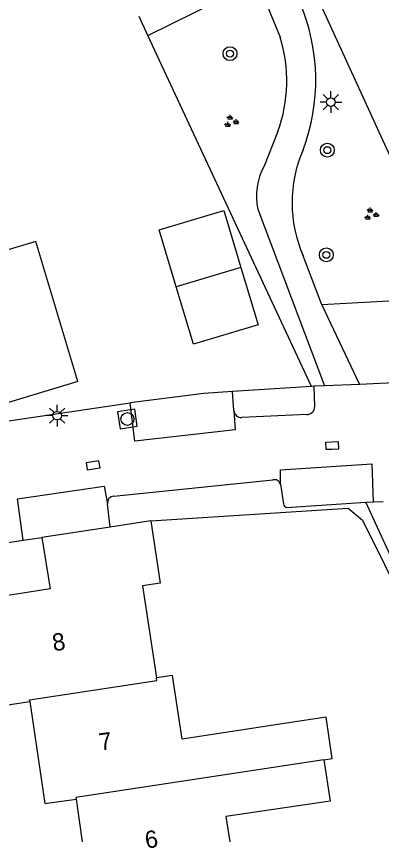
# Model space of a CAD drawing. Extents: x 128999 to 131010, y 395498 to 399007.
# Drawn here: x 130812.16 to 130833.26, y 395499.61 to 395547.75 of the extents above; entities that cross this region are included whole.
import ezdxf

# ---------------------------------------------------------------- set-up
doc = ezdxf.new("R2010")
doc.units = 0
for name, color, linetype in [('gg-afsc-erfafscheiding', 7, 'Continuous'), ('gg-anno-huisnummerreeks BGT', 7, 'Continuous'), ('gg-bbg-gedigitaliseerde bebouwing', 7, 'Continuous'), ('gg-bbg-gedigitaliseerde bijgebouw', 7, 'Continuous'), ('gg-bbg-hoofdgebouw', 7, 'Continuous'), ('gg-bbg-luifel en loopbrug', 7, 'Continuous'), ('gg-bbg-tussenscheiding', 7, 'Continuous'), ('gg-knt-onverhard', 7, 'Continuous'), ('gg-knt-verharding', 7, 'Continuous'), ('gg-knt-verharding nz', 7, 'Continuous'), ('gt-grn-groengrens', 7, 'Continuous'), ('gt-symb-boom', 7, 'Continuous'), ('gt-symb-groenvak', 7, 'Continuous'), ('gt-symb-kolk', 7, 'Continuous'), ('gt-symb-lichtmast', 7, 'Continuous'), ('gt-symb-rioolschacht', 7, 'Continuous')]:
    doc.layers.add(name, color=color, linetype=linetype)

# ---------------------------------------------------------------- blocks, each defined once
blk = doc.blocks.new('gt0-BOOM')
at = {"layer": 'gt-symb-boom'}
for radius in [0.4, 0.2]:
    blk.add_circle((0, 0), radius, dxfattribs=at)
blk = doc.blocks.new('gt0-LMAST')
at = {"layer": 'gt-symb-lichtmast'}
for p, q in [((-0.005, 0.246), (-0.005, 0.621)), ((-0.182, 0.173), (-0.447, 0.438)), ((0.172, 0.173), (0.437, 0.438)), ((-0.255, -0.004), (-0.63, -0.004)), ((-0.182, -0.181), (-0.447, -0.446)), ((-0.005, -0.254), (-0.005, -0.629)), ((0.437, -0.446), (0.172, -0.181)), ((0.245, -0.004), (0.62, -0.004))]:
    blk.add_line(p, q, dxfattribs=at)
blk.add_circle((-0.005, -0.004), 0.25, dxfattribs=at)
blk = doc.blocks.new('gt0-GRVAK')
at = {"layer": 'gt-symb-groenvak'}
for p, q in [((-0.11, 0.189), (-0.228, 0.24)), ((-0.182, 0.153), (0.088, 0.153)), ((-0.091, 0.211), (-0.156, 0.322)), ((-0.047, 0.214), (-0.047, 0.393)), ((-0.004, 0.211), (0.061, 0.322)), ((0.015, 0.189), (0.133, 0.24)), ((0.262, -0.052), (0.197, 0.059)), ((0.305, -0.049), (0.305, 0.13)), ((0.349, -0.052), (0.414, 0.059)), ((-0.245, -0.228), (-0.363, -0.177)), ((-0.318, -0.264), (-0.047, -0.264)), ((-0.226, -0.206), (-0.291, -0.095)), ((-0.183, -0.203), (-0.183, -0.024)), ((-0.139, -0.206), (-0.074, -0.095)), ((-0.12, -0.228), (-0.002, -0.177)), ((0.243, -0.074), (0.125, -0.023)), ((0.17, -0.11), (0.441, -0.11)), ((0.368, -0.074), (0.486, -0.023))]:
    blk.add_line(p, q, dxfattribs=at)
blk = doc.blocks.new('gt0-KOLK')
at = {"layer": 'gt-symb-kolk'}
blk.add_lwpolyline([(0, 0), (0.375, 0), (0.375, 0.4), (-0.375, 0.4), (-0.375, 0), (0, 0)], dxfattribs=at)
blk = doc.blocks.new('gt0-RS')
at = {"layer": 'gt-symb-rioolschacht'}
blk.add_lwpolyline([(-0.5, -0.5), (0.5, -0.5), (0.5, 0.5), (-0.5, 0.5)], close=True, dxfattribs=at)
blk.add_circle((0, 0), 0.375, dxfattribs=at)

msp = doc.modelspace()

# ---------------------------------------------------------------- linework, layer by layer
at = {"layer": 'gg-afsc-erfafscheiding'}
for p, q in [((130819.752, 395546.666), (130819.244, 395547.757)), ((130829.211, 395526.353), (130819.752, 395546.666))]:
    msp.add_line(p, q, dxfattribs=at)
for points in [[(130839.662, 395526.786), (130829.862, 395548.174), (130825.076, 395558.725), (130820.69, 395568.516)], [(130819.915, 395518.56), (130831.342, 395519.293), (130832.158, 395518.612), (130834.718, 395513.469), (130835.475, 395511.715), (130835.932, 395511.835)]]:
    msp.add_lwpolyline(points, dxfattribs=at)
at = {"layer": 'gg-bbg-gedigitaliseerde bebouwing'}
for points in [[(130815.694, 395526.641), (130813.26, 395534.74), (130811.34, 395534.15), (130810.271, 395537.61)], [(130819.915, 395518.56), (130820.456, 395514.968), (130819.44, 395514.81), (130820.25, 395509.48)], [(130827.76, 395506.85), (130821.73, 395505.94), (130821.17, 395509.62), (130820.25, 395509.48)], [(130829.928, 395504.74), (130830.416, 395504.814), (130830.054, 395507.198), (130827.76, 395506.85)], [(130829.928, 395504.74), (130830.29, 395502.35), (130824.26, 395501.45), (130824.482, 395500)]]:
    msp.add_lwpolyline(points, dxfattribs=at)
at = {"layer": 'gg-bbg-gedigitaliseerde bijgebouw'}
msp.add_line((130825.129, 395533.228), (130821.392, 395532.105), dxfattribs=at)
msp.add_lwpolyline([(130821.392, 395532.105), (130820.398, 395535.415), (130824.135, 395536.538), (130825.129, 395533.228)], dxfattribs=at)
at = {"layer": 'gg-bbg-hoofdgebouw'}
for p, q in [((130815.694, 395526.641), (130810.285, 395525)), ((130817.57, 395518.207), (130813.617, 395517.612)), ((130819.915, 395518.56), (130817.57, 395518.207)), ((130815.593, 395502.463), (130815.947, 395500))]:
    msp.add_line(p, q, dxfattribs=at)
for points in [[(130813.617, 395517.612), (130814.099, 395514.632), (130810.179, 395514.012), (130811.134, 395507.844), (130812.925, 395508.107)], [(130812.925, 395508.107), (130813.792, 395502.204), (130815.593, 395502.463)]]:
    msp.add_lwpolyline(points, dxfattribs=at)
at = {"layer": 'gg-bbg-luifel en loopbrug'}
msp.add_lwpolyline([(130825.129, 395533.228), (130826.124, 395529.918), (130822.387, 395528.795), (130821.392, 395532.105)], dxfattribs=at)
at = {"layer": 'gg-bbg-tussenscheiding'}
for points in [[(130812.925, 395508.107), (130812.909, 395508.214), (130820.274, 395509.321), (130820.25, 395509.48)], [(130829.928, 395504.74), (130815.579, 395502.562), (130815.593, 395502.463)]]:
    msp.add_lwpolyline(points, dxfattribs=at)
at = {"layer": 'gg-knt-onverhard'}
for p, q in [((130827.267, 395541.108), (130826.475, 395539.09)), ((130826.115, 395536.601), (130829.966, 395526.384)), ((130829.818, 395531.068), (130828.738, 395533.903))]:
    msp.add_line(p, q, dxfattribs=at)
msp.add_lwpolyline([(130819.752, 395546.666), (130825.304, 395549.415), (130826.209, 395549.473), (130827.393, 395546.555)], dxfattribs=at)
for centre, radius, start, end in [((130817.995, 395544.073), 11.465, 339.3759, 22.6568), ((130819.351, 395544.016), 8.433, 339.8287, 17.5211), ((130835.726, 395536.984), 7.637, 156.4505, 203.7924), ((130829.549, 395537.375), 3.52, 150.8379, 192.7021)]:
    msp.add_arc(centre, radius, start, end, dxfattribs=at)
at = {"layer": 'gg-knt-verharding'}
for p, q in [((130829.818, 395531.068), (130831.996, 395526.468)), ((130829.211, 395526.353), (130824.639, 395526.048)), ((130829.341, 395526.358), (130829.211, 395526.353)), ((130829.966, 395526.384), (130829.341, 395526.358)), ((130829.341, 395526.358), (130829.397, 395525.182)), ((130831.996, 395526.468), (130829.966, 395526.384)), ((130824.713, 395524.95), (130824.639, 395526.048)), ((130808.095, 395523.817), (130818.717, 395525.4)), ((130828.938, 395524.724), (130825.175, 395524.545)), ((130817.774, 395519.991), (130826.984, 395520.934)), ((130827.411, 395520.691), (130827.587, 395519.543)), ((130827.772, 395519.349), (130832.366, 395519.644)), ((130832.366, 395519.644), (130832.789, 395519.661)), ((130832.789, 395519.661), (130833.367, 395519.684)), ((130817.57, 395518.207), (130817.411, 395519.557)), ((130809.13, 395516.924), (130812.542, 395517.447)), ((130812.542, 395517.447), (130813.617, 395517.612))]:
    msp.add_line(p, q, dxfattribs=at)
for points in [[(130837.646, 395526.703), (130835.437, 395531.383), (130829.818, 395531.068)], [(130824.639, 395526.048), (130822.993, 395525.938), (130818.717, 395525.4)]]:
    msp.add_lwpolyline(points, dxfattribs=at)
for centre, radius, start, end in [((130825.164, 395524.998), 0.453, 186.0743, 271.4486), ((130828.953, 395525.168), 0.445, 268.1188, 1.7562), ((130827.087, 395520.618), 0.332, 12.6596, 108.0532), ((130817.794, 395519.605), 0.386, 93.0348, 187.1466), ((130827.825, 395519.585), 0.241, 189.9026, 257.3767)]:
    msp.add_arc(centre, radius, start, end, dxfattribs=at)
at = {"layer": 'gg-knt-verharding nz'}
msp.add_line((130837.646, 395526.703), (130831.996, 395526.468), dxfattribs=at)
for points in [[(130824.713, 395524.95), (130824.799, 395523.833), (130818.997, 395523.178), (130818.717, 395525.4)], [(130827.411, 395520.691), (130827.424, 395521.525), (130832.701, 395521.865), (130832.789, 395519.661)], [(130812.542, 395517.447), (130812.212, 395519.847), (130817.226, 395520.576), (130817.411, 395519.557)]]:
    msp.add_lwpolyline(points, dxfattribs=at)
at = {"layer": 'gt-grn-groengrens'}
msp.add_line((130835.932, 395511.835), (130832.366, 395519.644), dxfattribs=at)

# ---------------------------------------------------------------- block references
at = {"layer": 'gt-symb-boom'}
for p in [(130824.5, 395545.606), (130830.13, 395540.022), (130830.072, 395533.962)]:
    msp.add_blockref('gt0-BOOM', p, dxfattribs=at)
at = {"layer": 'gt-symb-groenvak'}
for p in [(130824.551, 395541.676), (130832.657, 395536.304)]:
    msp.add_blockref('gt0-GRVAK', p, dxfattribs=at)
at = {"layer": 'gt-symb-kolk'}
for p, rotation in [((130830.419, 395522.724), 2.4074138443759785), ((130816.61, 395521.585), 8.802804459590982)]:
    msp.add_blockref('gt0-KOLK', p, dxfattribs=dict(at, rotation=rotation))
at = {"layer": 'gt-symb-lichtmast'}
for p in [(130830.34, 395542.806), (130814.503, 395524.66)]:
    msp.add_blockref('gt0-LMAST', p, dxfattribs=at)
at = {"layer": 'gt-symb-rioolschacht', "rotation": 8.162509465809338}
msp.add_blockref('gt0-RS', (130818.564, 395524.463), dxfattribs=at)

# ---------------------------------------------------------------- texts
at = {"layer": 'gg-anno-huisnummerreeks BGT'}
for s, rotation, p in [('8', 8.8, (130814.298, 395511.015)), ('7', 8.3, (130816.994, 395505.264)), ('6', 8.2, (130819.653, 395499.595))]:
    msp.add_text(s, height=1, rotation=rotation, dxfattribs=at).set_placement(p)

doc.saveas('drawing.dxf')
